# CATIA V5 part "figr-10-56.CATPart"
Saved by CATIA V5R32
Part number: Part1
Bounding box of the stored display mesh (mm): x -101.896 to 127.212, y -67.72 to 67.298, z 0 to 0
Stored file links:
  D:\PROJECTS\Project 2022\CATIA V5 6R 2022\Resources\Part Files\c10_catia_v5_6r2022_prt\c10_catia_v5_6r2022_prt\figr-10-56.CATPart
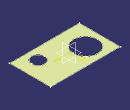
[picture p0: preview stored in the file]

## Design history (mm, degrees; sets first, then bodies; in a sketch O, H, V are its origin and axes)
Body1 (main body)
  Sketch1 on xy-plane, origin (0, 0, 0), H (1, 0, 0), V (0, 1, 0)
    line L1 (-101.8963, 67.298) -> (127.2122, 67.298)
    line L2 (127.2122, 67.298) -> (127.2122, -67.7199)
    line L3 (127.2122, -67.7199) -> (-101.8963, -67.7199)
    line L4 (-101.8963, -67.7199) -> (-101.8963, 67.298)
    horizontal: L1 H, L3 H
    vertical: L2 V, L4 V
  Sketch2 on xy-plane, origin (0, 0, 0), H (1, 0, 0), V (0, 1, 0)
    circle A1 centre (-45.2964, 9.2296) radius 39.3004
    circle A2 centre (71.0804, -29.9585) radius 20.9926
  Fill1: Boundary Sketch1, InnerBoundaries {fillinnerboundary Boundaries Sketch2}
